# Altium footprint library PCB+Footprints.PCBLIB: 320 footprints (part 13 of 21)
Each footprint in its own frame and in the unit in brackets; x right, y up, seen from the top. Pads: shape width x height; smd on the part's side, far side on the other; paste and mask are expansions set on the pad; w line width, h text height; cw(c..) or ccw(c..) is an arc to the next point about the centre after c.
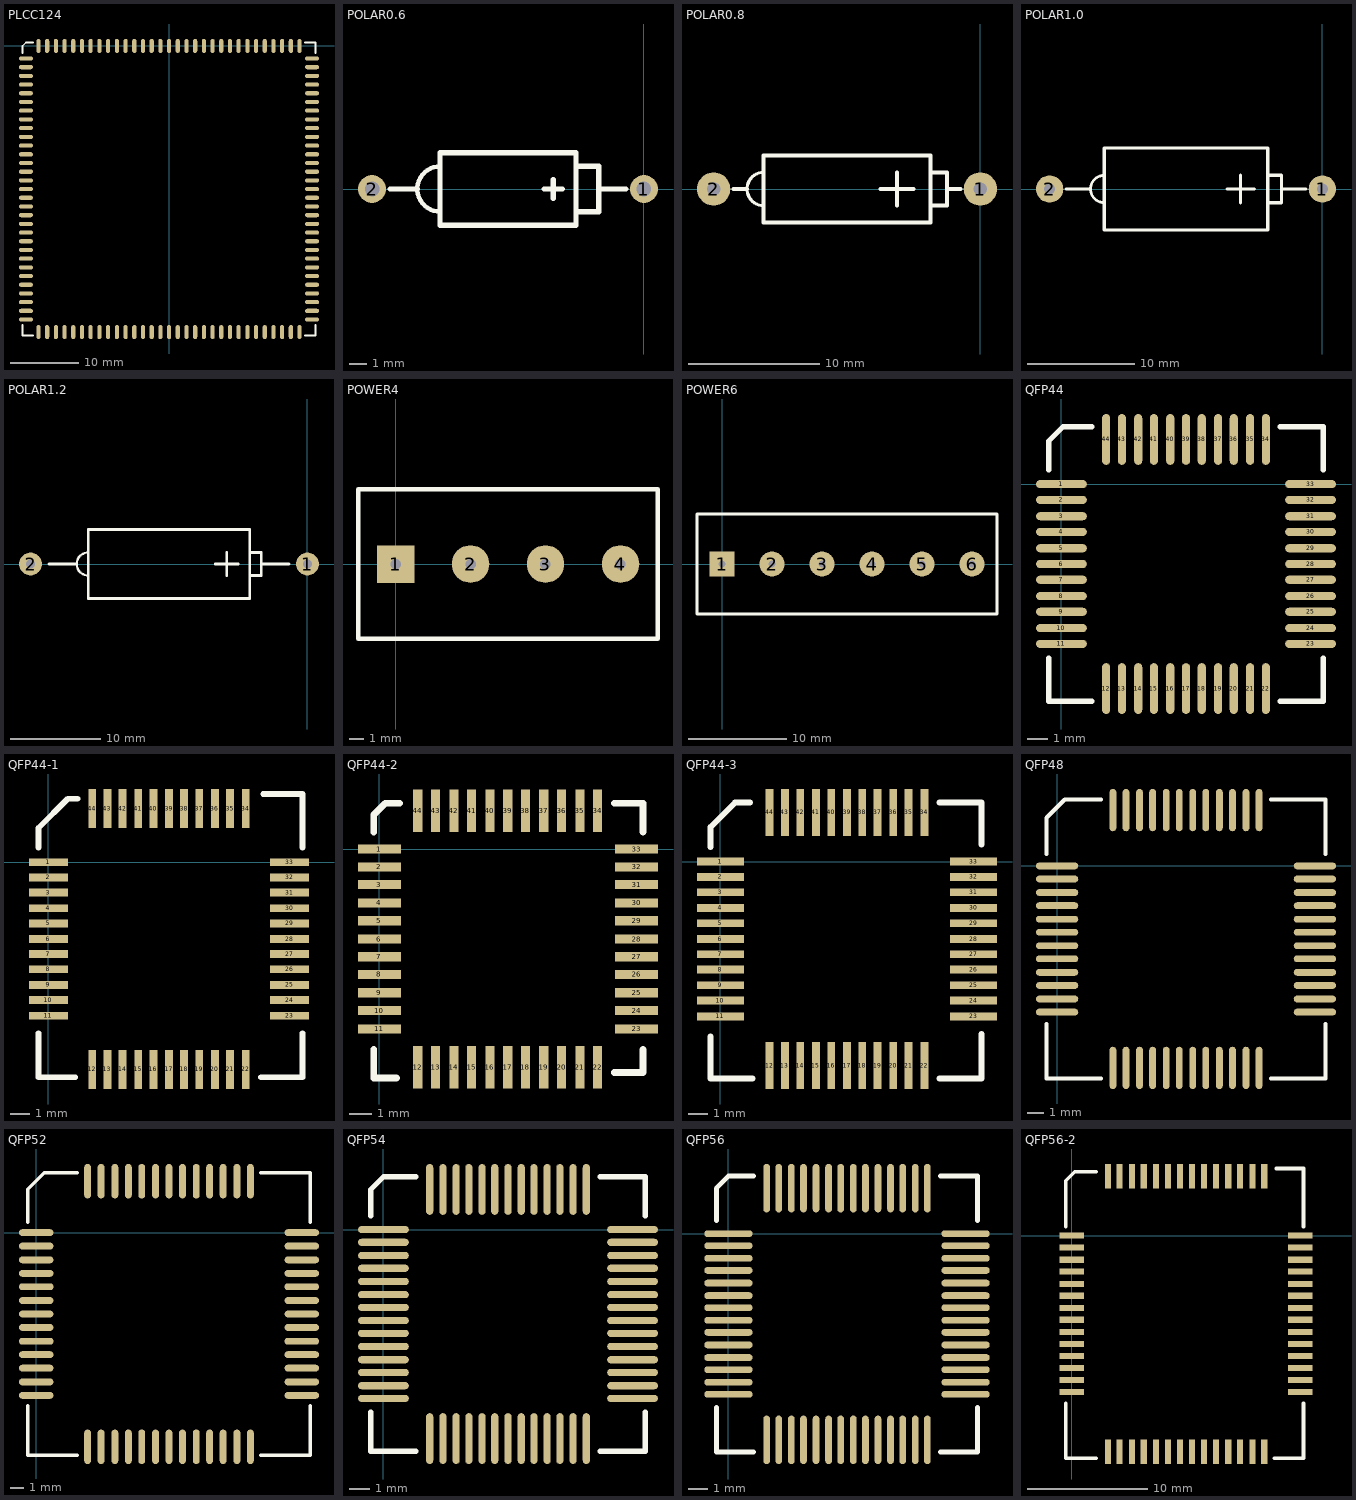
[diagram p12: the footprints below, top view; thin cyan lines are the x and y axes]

## PLCC124 [mil]
pads (124):
  oct 24x80 smd: 1(0,0)
  oval 24x80 smd: 2(-50,0) 3(-100,0) 4(-150,0) 5(-200,0) 6(-250,0) 7(-300,0) 8(-351,0) 9(-401,0) 10(-451,0) 11(-501,0) 12(-551,0) 13(-601,0) 14(-651,0) 15(-701,0) 16(-751,0) 48(-751,-1645) 49(-701,-1645) 50(-651,-1645) 51(-601,-1645) 52(-551,-1645) 53(-501,-1645) 54(-451,-1645) 55(-401,-1645) 56(-351,-1645) 57(-300,-1645) 58(-250,-1645) 59(-200,-1645) 60(-150,-1645) 61(-100,-1645) 62(-50,-1645) 63(0,-1645) 64(50,-1645) 65(100,-1645) 66(150,-1645) 67(200,-1645) 68(250,-1645) 69(300,-1645) 70(350,-1645) 71(400,-1645) 72(450,-1645) 73(500,-1645) 74(550,-1645) 75(600,-1645) 76(650,-1645) 77(700,-1645) 78(750,-1645) 110(750,0) 111(700,0) 112(650,0) 113(600,0) 114(550,0) 115(500,0) 116(450,0) 117(400,0) 118(350,0) 119(300,0) 120(250,0) 121(200,0) 122(150,0) 123(100,0) 124(50,0)
  oval 80x24 smd: 17(-823,-72) 18(-823,-122) 19(-823,-172) 20(-823,-222) 21(-823,-272) 22(-823,-322) 23(-823,-372) 24(-823,-422) 25(-823,-472) 26(-823,-523) 27(-823,-573) 28(-823,-623) 29(-823,-673) 30(-823,-723) 31(-823,-773) 32(-823,-823) 33(-823,-873) 34(-823,-923) 35(-823,-973) 36(-823,-1023) 37(-823,-1073) 38(-823,-1123) 39(-823,-1173) 40(-823,-1223) 41(-823,-1273) 42(-823,-1323) 43(-823,-1373) 44(-823,-1423) 45(-823,-1473) 46(-823,-1523) 47(-823,-1573) 79(822,-1573) 80(822,-1523) 81(822,-1473) 82(822,-1423) 83(822,-1373) 84(822,-1323) 85(822,-1273) 86(822,-1223) 87(822,-1173) 88(822,-1123) 89(822,-1073) 90(822,-1023) 91(822,-973) 92(822,-923) 93(822,-873) 94(822,-823) 95(822,-773) 96(822,-723) 97(822,-673) 98(822,-623) 99(822,-573) 100(822,-523) 101(822,-472) 102(822,-422) 103(822,-372) 104(822,-322) 105(822,-272) 106(822,-222) 107(822,-172) 108(822,-122) 109(822,-72)
TopOverlay:
  lines w10: -843,-1605 -843,-1665 -783,-1665 ; -843,-40 -843,0 -823,20 -783,20 ; 782,-1665 842,-1665 842,-1605 ; 782,20 842,20 842,-40

## POLAR0.6 [mil]
pads (2):
  round 62 hole 32: 1(0,0) 2(-600,0)
TopOverlay:
  lines w10: -450,-50 cw(c-450,0) -450,50
  lines w12: -560,0 -500,0 ; -220,0 -180,0 ; -200,-20 -200,20 ; -150,-50 -100,-50 -100,50 -150,50 ; -100,0 -40,0 ; -450,-80 -150,-80 -150,80 -450,80 -450,-80

## POLAR0.8 [mil]
pads (2):
  round 100 hole 40: 1(0,0) 2(-800,0)
TopOverlay:
  lines w10: -650,-50 cw(c-650,0) -650,50
  lines w12: -740,0 -700,0 ; -300,0 -200,0 ; -250,-50 -250,50 ; -150,-50 -100,-50 -100,50 -150,50 ; -100,0 -60,0 ; -650,-100 -150,-100 -150,100 -650,100 -650,-100

## POLAR1.0 [mil]
pads (2):
  round 100 hole 40: 1(0,0) 2(-1000,0)
TopOverlay:
  lines w10: -800,-50 cw(c-800,0) -800,50
  lines w12: -940,0 -850,0 ; -350,0 -250,0 ; -300,-50 -300,50 ; -200,-50 -150,-50 -150,50 -200,50 ; -150,0 -60,0 ; -800,-150 -200,-150 -200,150 -800,150 -800,-150

## POLAR1.2 [mil]
pads (2):
  round 100 hole 40: 1(0,0) 2(-1200,0)
TopOverlay:
  lines w10: -950,-50 cw(c-950,0) -950,50
  lines w12: -1120,0 -1000,0 ; -400,0 -300,0 ; -350,-50 -350,50 ; -250,-50 -200,-50 -200,50 -250,50 ; -200,0 -80,0 ; -950,-150 -250,-150 -250,150 -950,150 -950,-150

## POWER4 [mil]
pads (4):
  rect 100x100 hole 28: 1(0,0)
  round 100 hole 28: 2(200,0) 3(400,0) 4(600,0)
TopOverlay:
  lines w12: -100,-200 700,-200 700,200 -100,200 -100,-200

## POWER6 [mil]
pads (6):
  rect 100x100 hole 28: 1(0,0)
  round 100 hole 28: 2(200,0) 3(400,0) 4(600,0) 5(800,0) 6(1000,0)
TopOverlay:
  lines w12: -100,-200 1100,-200 1100,200 -100,200 -100,-200

## QFP44 [mil]
pads (44):
  oval 100x16 smd: 1(0,0) 2(0,-31) 3(0,-63) 4(0,-94) 5(0,-126) 6(0,-157) 7(0,-188) 8(0,-220) 9(0,-251) 10(0,-283) 11(0,-314) 23(490,-314) 24(490,-283) 25(490,-251) 26(490,-220) 27(490,-188) 28(490,-157) 29(490,-126) 30(490,-94) 31(490,-63) 32(490,-31) 33(490,0)
  oval 16x100 smd: 12(88,-402) 13(119,-402) 14(151,-402) 15(182,-402) 16(214,-402) 17(245,-402) 18(276,-402) 19(308,-402) 20(339,-402) 21(371,-402) 22(402,-402) 34(402,88) 35(371,88) 36(339,88) 37(308,88) 38(276,88) 39(245,88) 40(214,88) 41(182,88) 42(151,88) 43(119,88) 44(88,88)
TopOverlay:
  lines w10: -25,-342 -25,-427 60,-427 ; -25,28 -25,85 3,113 60,113 ; 430,-427 515,-427 515,-342 ; 430,113 515,113 515,28

## QFP44-1 [mil]
pads (44):
  rect 80x16 smd: 1(0,0) 2(0,-31) 3(0,-62) 4(0,-94) 5(0,-125) 6(0,-157) 7(0,-188) 8(0,-219) 9(0,-251) 10(0,-282) 11(0,-314) 23(494,-314) 24(494,-282) 25(494,-251) 26(494,-219) 27(494,-188) 28(494,-157) 29(494,-125) 30(494,-94) 31(494,-62) 32(494,-31) 33(494,0)
  rect 16x80 smd: 12(90,-424) 13(121,-424) 14(152,-424) 15(184,-424) 16(215,-424) 17(247,-424) 18(278,-424) 19(309,-424) 20(341,-424) 21(372,-424) 22(404,-424) 34(404,110) 35(372,110) 36(341,110) 37(309,110) 38(278,110) 39(247,110) 40(215,110) 41(184,110) 42(152,110) 43(121,110) 44(90,110)
TopOverlay:
  lines w12: -20,-350 -20,-440 55,-440 ; -20,30 -20,70 40,130 60,130 ; 435,-440 520,-440 520,-350 ; 440,140 520,140 520,30

## QFP44-2 [mil]
pads (44):
  rect 75x16 smd: 1(0,0) 2(0,-31) 3(0,-62) 4(0,-94) 5(0,-125) 6(0,-157) 7(0,-188) 8(0,-219) 9(0,-251) 10(0,-282) 11(0,-314) 23(449,-314) 24(449,-282) 25(449,-251) 26(449,-219) 27(449,-188) 28(449,-157) 29(449,-125) 30(449,-94) 31(449,-62) 32(449,-31) 33(449,0)
  rect 16x75 smd: 12(67,-381) 13(98,-381) 14(130,-381) 15(161,-381) 16(193,-381) 17(224,-381) 18(255,-381) 19(287,-381) 20(318,-381) 21(350,-381) 22(381,-381) 34(381,67) 35(350,67) 36(318,67) 37(287,67) 38(255,67) 39(224,67) 40(193,67) 41(161,67) 42(130,67) 43(98,67) 44(67,67)
TopOverlay:
  lines w12: -10,-350 -10,-400 30,-400 ; -10,30 -10,60 10,80 35,80 ; 410,-390 460,-390 460,-350 ; 410,80 460,80 460,30

## QFP44-3 [mil]
pads (44):
  rect 95x16 smd: 1(0,0) 2(0,-31) 3(0,-62) 4(0,-94) 5(0,-125) 6(0,-157) 7(0,-188) 8(0,-219) 9(0,-251) 10(0,-282) 11(0,-314) 23(514,-314) 24(514,-282) 25(514,-251) 26(514,-219) 27(514,-188) 28(514,-157) 29(514,-125) 30(514,-94) 31(514,-62) 32(514,-31) 33(514,0)
  rect 16x95 smd: 12(100,-414) 13(131,-414) 14(162,-414) 15(194,-414) 16(225,-414) 17(257,-414) 18(288,-414) 19(319,-414) 20(351,-414) 21(382,-414) 22(414,-414) 34(414,100) 35(382,100) 36(351,100) 37(319,100) 38(288,100) 39(257,100) 40(225,100) 41(194,100) 42(162,100) 43(131,100) 44(100,100)
TopOverlay:
  lines w12: -20,-355 -20,-440 65,-440 ; -20,30 -20,70 30,120 60,120 ; 445,-440 530,-440 530,-350 ; 445,120 530,120 530,35

## QFP48 [mil]
pads (48):
  oval 100x16 smd: 1(0,0) 2(0,-31) 3(0,-63) 4(0,-94) 5(0,-126) 6(0,-157) 7(0,-189) 8(0,-220) 9(0,-252) 10(0,-283) 11(0,-315) 12(0,-346) 25(610,-346) 26(610,-315) 27(610,-283) 28(610,-252) 29(610,-220) 30(610,-189) 31(610,-157) 32(610,-126) 33(610,-94) 34(610,-63) 35(610,-31) 36(610,0)
  oval 16x100 smd: 13(132,-478) 14(163,-478) 15(195,-478) 16(226,-478) 17(258,-478) 18(289,-478) 19(321,-478) 20(352,-478) 21(384,-478) 22(415,-478) 23(447,-478) 24(478,-478) 37(478,132) 38(447,132) 39(415,132) 40(384,132) 41(352,132) 42(321,132) 43(289,132) 44(258,132) 45(226,132) 46(195,132) 47(163,132) 48(132,132)
TopOverlay:
  lines w10: -25,-374 -25,-503 104,-503 ; -25,28 -25,114 18,157 104,157 ; 506,-503 635,-503 635,-374 ; 506,157 635,157 635,28

## QFP52 [mil]
pads (52):
  oval 100x20 smd: 1(0,0) 2(0,-39) 3(0,-79) 4(0,-118) 5(0,-157) 6(0,-197) 7(0,-236) 8(0,-275) 9(0,-315) 10(0,-354) 11(0,-393) 12(0,-433) 13(0,-472) 27(770,-472) 28(770,-433) 29(770,-393) 30(770,-354) 31(770,-315) 32(770,-275) 33(770,-236) 34(770,-197) 35(770,-157) 36(770,-118) 37(770,-79) 38(770,-39) 39(770,0)
  oval 20x100 smd: 14(149,-621) 15(188,-621) 16(228,-621) 17(267,-621) 18(306,-621) 19(346,-621) 20(385,-621) 21(424,-621) 22(464,-621) 23(503,-621) 24(542,-621) 25(582,-621) 26(621,-621) 40(621,149) 41(582,149) 42(542,149) 43(503,149) 44(464,149) 45(424,149) 46(385,149) 47(346,149) 48(306,149) 49(267,149) 50(228,149) 51(188,149) 52(149,149)
TopOverlay:
  lines w10: -25,-502 -25,-646 119,-646 ; -25,30 -25,126 23,174 119,174 ; 651,-646 795,-646 795,-502 ; 651,174 795,174 795,30

## QFP54 [mil]
pads (54):
  oval 100x14 smd: 1(0,0) 2(0,-25) 3(0,-51) 4(0,-76) 5(0,-102) 6(0,-128) 7(0,-153) 8(0,-179) 9(0,-204) 10(0,-230) 11(0,-256) 12(0,-281) 13(0,-307) 14(0,-332) 28(490,-332) 29(490,-307) 30(490,-281) 31(490,-256) 32(490,-230) 33(490,-204) 34(490,-179) 35(490,-153) 36(490,-128) 37(490,-102) 38(490,-76) 39(490,-51) 40(490,-25) 41(490,0)
  oval 14x100 smd: 15(91,-411) 16(117,-411) 17(143,-411) 18(168,-411) 19(194,-411) 20(219,-411) 21(245,-411) 22(271,-411) 23(296,-411) 24(322,-411) 25(347,-411) 26(373,-411) 27(399,-411) 42(399,79) 43(373,79) 44(347,79) 45(322,79) 46(296,79) 47(271,79) 48(245,79) 49(219,79) 50(194,79) 51(168,79) 52(143,79) 53(117,79) 54(91,79)
TopOverlay:
  lines w10: -25,-359 -25,-436 64,-436 ; -25,27 -25,79 0,104 64,104 ; 426,-436 515,-436 515,-359 ; 426,104 515,104 515,27

## QFP56 [mil]
pads (56):
  oval 100x14 smd: 1(0,0) 2(0,-25) 3(0,-51) 4(0,-76) 5(0,-102) 6(0,-128) 7(0,-153) 8(0,-179) 9(0,-204) 10(0,-230) 11(0,-256) 12(0,-281) 13(0,-307) 14(0,-332) 29(490,-332) 30(490,-307) 31(490,-281) 32(490,-256) 33(490,-230) 34(490,-204) 35(490,-179) 36(490,-153) 37(490,-128) 38(490,-102) 39(490,-76) 40(490,-51) 41(490,-25) 42(490,0)
  oval 14x100 smd: 15(79,-426) 16(104,-426) 17(130,-426) 18(155,-426) 19(181,-426) 20(207,-426) 21(232,-426) 22(258,-426) 23(283,-426) 24(309,-426) 25(335,-426) 26(360,-426) 27(386,-426) 28(411,-426) 43(411,94) 44(386,94) 45(360,94) 46(335,94) 47(309,94) 48(283,94) 49(258,94) 50(232,94) 51(207,94) 52(181,94) 53(155,94) 54(130,94) 55(104,94) 56(79,94)
TopOverlay:
  lines w10: -25,-359 -25,-451 52,-451 ; -25,27 -25,94 0,119 52,119 ; 438,-451 515,-451 515,-359 ; 438,119 515,119 515,27

## QFP56-2 [mil]
pads (56):
  rect 80x20 smd: 1(0,0) 2(0,-39) 3(0,-79) 4(0,-118) 5(0,-158) 6(0,-197) 7(0,-237) 8(0,-276) 9(0,-316) 10(0,-355) 11(0,-395) 12(0,-434) 13(0,-474) 14(0,-513) 29(749,-513) 30(749,-474) 31(749,-434) 32(749,-395) 33(749,-355) 34(749,-316) 35(749,-276) 36(749,-237) 37(749,-197) 38(749,-158) 39(749,-118) 40(749,-79) 41(749,-39) 42(749,0)
  rect 20x80 smd: 15(118,-709) 16(157,-709) 17(197,-709) 18(236,-709) 19(276,-709) 20(315,-709) 21(355,-709) 22(394,-709) 23(434,-709) 24(473,-709) 25(513,-709) 26(552,-709) 27(592,-709) 28(631,-709) 43(631,195) 44(592,195) 45(552,195) 46(513,195) 47(473,195) 48(434,195) 49(394,195) 50(355,195) 51(315,195) 52(276,195) 53(236,195) 54(197,195) 55(157,195) 56(118,195)
TopOverlay:
  lines w12: -20,-550 -20,-730 80,-730 ; -20,30 -20,180 10,210 80,210 ; 665,-730 760,-730 760,-550 ; 670,220 760,220 760,30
